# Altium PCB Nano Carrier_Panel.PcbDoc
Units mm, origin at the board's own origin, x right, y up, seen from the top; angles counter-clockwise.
Board outline 171.92 x 183 mm, 4 copper layers (Top, PWR, MID, Bottom), stack 1.612 mm thick; 0 components, 48 nets, 22 pads, 0 vias.
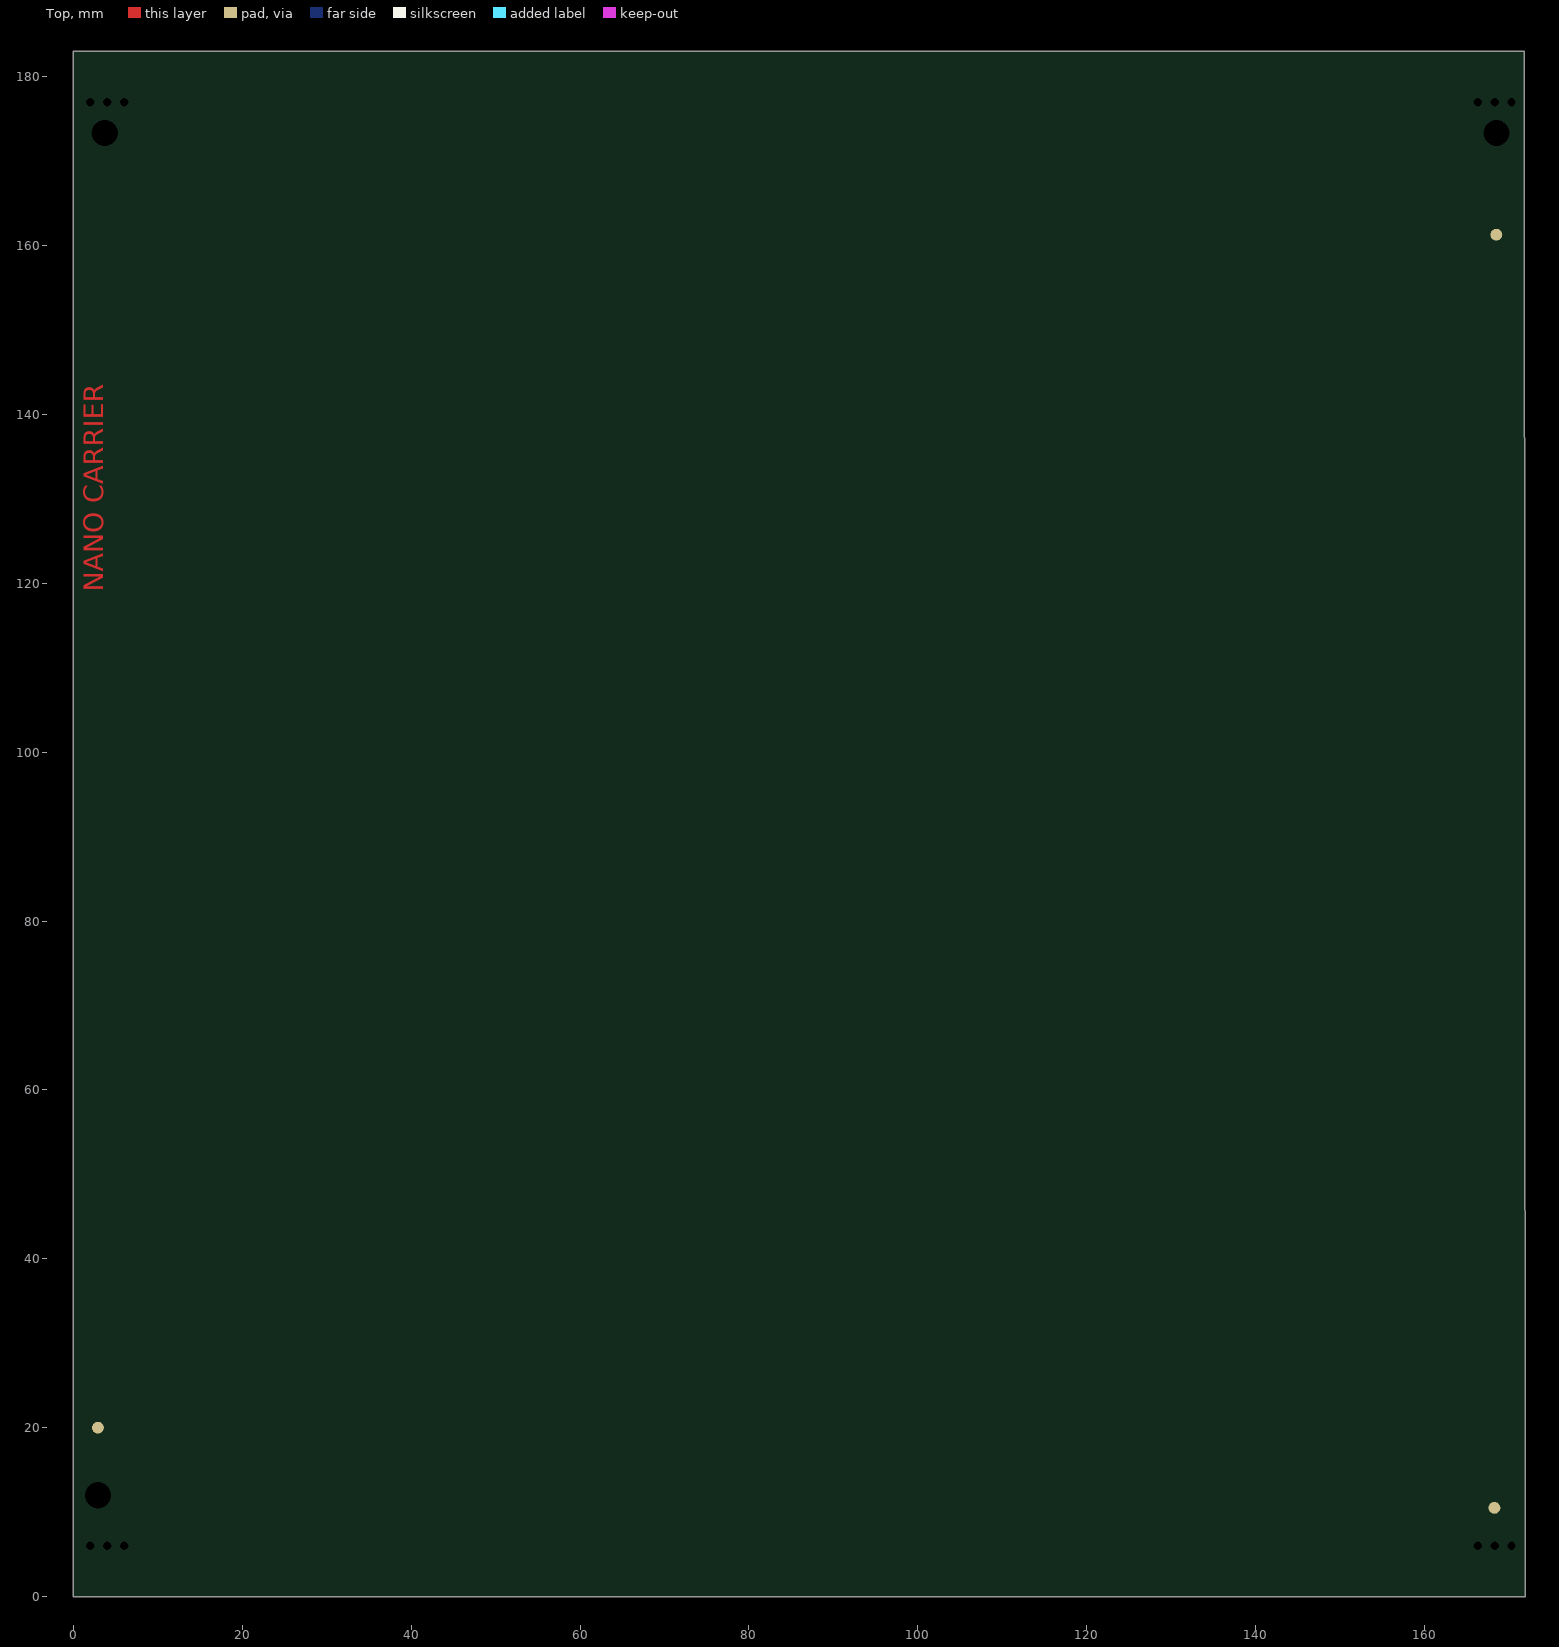
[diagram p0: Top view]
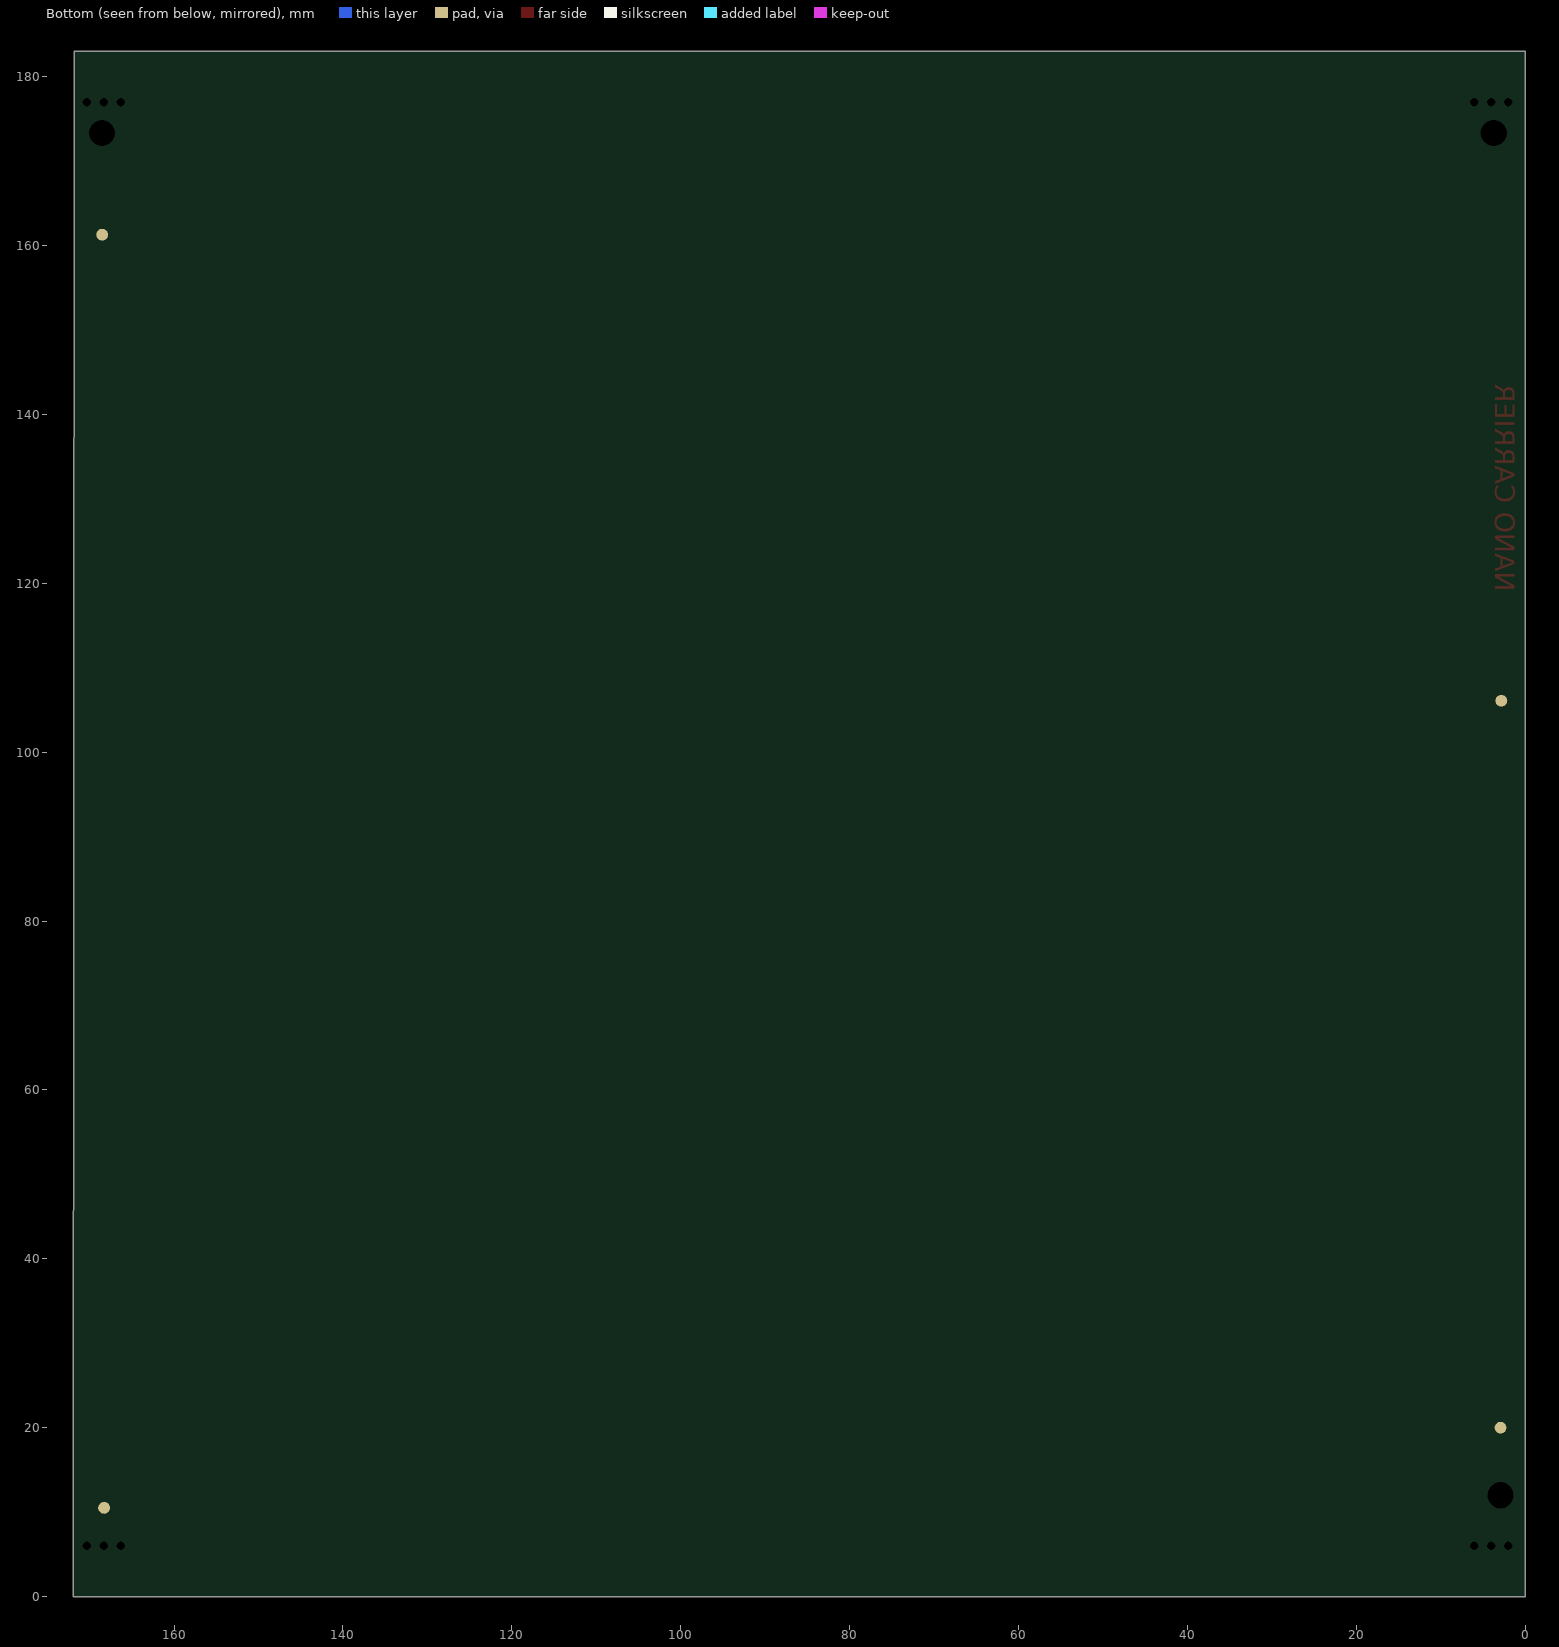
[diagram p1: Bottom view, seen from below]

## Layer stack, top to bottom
Top Solder: solder mask 0.01, Solder Resist, Dk 3.5
Top: signal copper 0.035
Dielectric 1: core 0.356, FR-4, Dk 4.8
PWR: signal copper 0.035
Dielectric3: core 0.76, FR-4, Dk 4.8
MID: signal copper 0.035
Dielectric2: prepreg 0.356, FR-4, Dk 4.8
Bottom: signal copper 0.035
Bottom Solder: solder mask 0.01, Solder Resist, Dk 3.5

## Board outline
171.816,183 0,183 0,0 171.923,0

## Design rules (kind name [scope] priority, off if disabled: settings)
BoardOutlineClearance [not HasFootprint('PH1-15-UA (CASTELL)') and not OnLayer('TopOverlay') and not OnLayer('BottomOverlay')] p1: gap=0.254 ignorepadtopadclearanceinfootprint=FALSE except(0: Arc-SplitContinuation Track-SplitContinuation SMDPad-SplitContinuation THPad-SplitContinuation Via-SplitContinuation Fill-SplitContinuation Poly-SplitContinuation Region-SplitContinuation Text-SplitContinuation)
BoardOutlineClearance mdCopperDimension [not IsKeepOut and not HasFootprint('PH1-15-UA (CASTELL)') and not OnLayer('TopOverlay') and not OnLayer('BottomOverlay')] p2: gap=0.254 ignorepadtopadclearanceinfootprint=FALSE except(0: Arc-SplitContinuation Track-SplitContinuation SMDPad-SplitContinuation THPad-SplitContinuation Via-SplitContinuation Fill-SplitContinuation Poly-SplitContinuation Region-SplitContinuation Text-SplitContinuation)
Clearance Clearance_for_PolygonClass_Isolate_0 [InPolygonClass('Isolate_0')] p1 off: gap=0 ignorepadtopadclearanceinfootprint=FALSE except(0.254: Poly-Hole)
Clearance Clearance_for_PolygonClass_Isolate_3.94 [InPolygonClass('Isolate_3.94')] p2 off: gap=0 ignorepadtopadclearanceinfootprint=FALSE except(0.1: Arc-Poly Track-Poly SMDPad-Poly THPad-Poly Via-Poly Fill-Poly Poly-Poly Poly-Region Poly-Text; 0.254: Poly-Hole)
Clearance [not Keepout vs not Keepout] p3: gap=0.138 ignorepadtopadclearanceinfootprint=TRUE except(0.127: SMDPad-SMDPad SMDPad-THPad SMDPad-Via THPad-THPad THPad-Via Via-Via)
Clearance "Clearance (Same Net)" [All] p4: gap=0 ignorepadtopadclearanceinfootprint=TRUE
Clearance Clearance_for_NetClass_usb [InNetClass('usb') vs InNetClass('usb')] p5: gap=0.127 ignorepadtopadclearanceinfootprint=FALSE
ComponentClearance ComponentClearance_HEADER [InComponent('JP2') or InComponent('JP3') vs InComponent('JP2') or InComponent('JP3')] p1: gap=0 collisioncheckmode=3 verticalgap=0 showdistances=FALSE
ComponentClearance ComponentClearance_1 [All] p2: gap=0.254 collisioncheckmode=3 verticalgap=0.254 showdistances=FALSE
DiffPairsRouting [All] p1: maxlimit=0.3 minlimit=0.1 mostfreqgap=0.254 toplayer_prefgap=0.15 toplayer_minwidth=0.2 toplayer_maxwidth=0.254 toplayer_prefwidth=0.2 midlayer1_maxgap=0.2 midlayer1_prefgap=0.15 midlayer1_minwidth=0.2 midlayer1_maxwidth=0.254 midlayer1_prefwidth=0.2 midlayer2_mingap=0.254 midlayer2_maxgap=0.254 midlayer2_minwidth=0.381 midlayer2_maxwidth=0.381 midlayer2_prefwidth=0.381 bottomlayer_prefgap=0.15 bottomlayer_minwidth=0.2 bottomlayer_maxwidth=0.254 bottomlayer_prefwidth=0.2 maxuncoupledlength=12.7
HoleSize HoleSize_For_NetClass_usb [InNetClass('usb')] p1: absolutevalues=TRUE maxlimit=0.19 minlimit=0.19 maxpercent=80.000 minpercent=20.000
HoleSize [All] p2: absolutevalues=TRUE maxlimit=2540 minlimit=0.19 maxpercent=80.000 minpercent=20.000
HoleToHoleClearance mdDrill [All] p1: gap=0.203 allowstackedmicrovias=TRUE
MinimumSolderMaskSliver [All] p1 off: minsoldermaskwidth=0.254
PasteMaskExpansion Expansion_SMDPaste_OFF [InPadClass('All Pads')] p1: expansion=0
PasteMaskExpansion mlMinCreamFrame [All] p2: expansion=0
PolygonConnect PolygonConnect_For_PolygonThermal_ON_Width100000_Gap100000 [InPolygonClass('PolygonThermal_ON_Width100000_Gap100000') vs Not IsVia] p1: connectstyle=Relief reliefconductorwidth=0.254 reliefentries=4 polygonreliefangle="90 Angle" airgapwidth=0.254
PolygonConnect PolygonConnect_For_PolygonThermal_ON_Width98400_Gap100000 [InPolygonClass('PolygonThermal_ON_Width98400_Gap100000') vs Not IsVia] p2: connectstyle=Relief reliefconductorwidth=0.25 reliefentries=4 polygonreliefangle="90 Angle" airgapwidth=0.254
PolygonConnect ThermalVias [IsVia] p3: connectstyle=Relief reliefconductorwidth=0.254 reliefentries=4 polygonreliefangle="90 Angle" airgapwidth=0.1
PolygonConnect [All] p4: connectstyle=Relief reliefconductorwidth=0.254 reliefentries=4 polygonreliefangle="90 Angle" airgapwidth=0.1
RoomDefinition NANOWANV1_0 [InComponentClass('NANOWANV1_0')] p1 off: confinementstyle=ConfineIn formatcopy=TRUE lockcomponents=FALSE outline -0.592,-0.254 60.495,-0.254 60.495,22.225 -0.592,22.225
RoutingVias [All] p1: holewidth=0.3 width=0.5 viastyle="Through Hole" minholewidth=0.2 minwidth=0.4 maxholewidth=0.5 maxwidth=0.7
SilkToSolderMaskClearance [IsPad] p1 off: minsilkscreentomaskgap=0.254 clearancetoexposedcopper=TRUE
SolderMaskExpansion Expansion_SMDSolder_OFF [InPadClass('SMDSolder_OFF')] p1: expansion=0 istentingtop=FALSE
SolderMaskExpansion mlMinStopFrame [All] p2: expansion=0.102 istentingtop=FALSE
UnRoutedNet [All] p1: checkbadconnections=TRUE
Width Width_For_NetClass_usb [InNetClass('usb')] p1: maxlimit=0.6 minlimit=0.19 preferedwidth=0.254 toplayer_minwidth=0.2 midlayer1_minwidth=0.2 midlayer2_maxwidth=0.254 midlayer2_prefwidth=0.19 bottomlayer_minwidth=0.2 minimp=50.000000 maximp=50.000000 favimp=50.000000
Width [All] p2: maxlimit=254 minlimit=0.1 preferedwidth=0.2 midlayer2_prefwidth=0.152 minimp=50.000000 maximp=50.000000 favimp=50.000000
22 further rules are at their usual default settings.

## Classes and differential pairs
pad class SMDSolder_OFF: U1-EP
pad class SMDPaste_OFF: U1-EP
differential pair USB: +USB_P -USB_N

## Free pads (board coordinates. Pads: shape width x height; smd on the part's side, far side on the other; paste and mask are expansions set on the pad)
  round 1.4 smd far side paste-5 mask+1: 21(2.8,106.1) 21(2.9,20) 21(168.528,161.3)
  round 1.4 smd paste-5 mask+1: 21(2.9,20) 21(168.3,10.5) 21(168.528,161.3)
  round 1.4 smd far side paste+0 mask+1: 21(168.3,10.5)
  round 0 hole 3.1 unplated: 22(2.9,12) 22(3.703,173.351) 22(168.528,173.351)
  round 0 hole 1 unplated: H1(2,6) H1(2,177) H1(4,6) H1(4,177) H1(6,6) H1(6,177) H1(166.325,6) H1(166.325,177) H1(168.325,6) H1(168.325,177) H1(170.325,6) H1(170.325,177)

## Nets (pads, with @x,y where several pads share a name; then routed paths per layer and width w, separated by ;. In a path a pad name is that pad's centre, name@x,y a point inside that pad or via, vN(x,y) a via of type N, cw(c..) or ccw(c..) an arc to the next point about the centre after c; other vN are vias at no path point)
+3V3: 
+3V3_HE: 
+5V: 
+VBUCK: 
A0: 
A1: 
A2: 
A3: 
AREF: 
BOOT0: 
D2: 
D3~: 
D5~: 
D6~: 
D9~: 
D10: 
GND: 
MISO: 
MOSI: 
NetC1_2: 
NetC5_2: 
NetC6_2: 
NetDL1_A: 
NetDL2_A: 
NetL1_1: 
NetM1_4: 
NetM1_10: 
NetM1_20: 
NetM1_45: 
NetM1_46: 
NetM1_47: 
NetM1_48: 
NetQ1_G1: 
NetQ1_S1: 
NetR6_2: 
NetR9_2: 
RESETN: 
RX1: 
SCK: 
SCL: 
SDA: 
SWCLK: 
SWDIO: 
TX1: 
USB_N: 
USB_P: 
VIN: 
VUSB: 

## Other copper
Top:
  text "NANO CARRIER" at 4.3,119 h4 r90

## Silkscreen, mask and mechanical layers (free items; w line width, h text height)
Top Solder:
  text "NANO CARRIER" at 4.3,119 h4 r90
  text "SN" at 170.9,18.6 h4 r90
Drill Guide:
  drawing of 295 lines, arcs and shapes, not listed
  text "Layer" at 193.088,109.344 h1.52
  text "Name" at 203.5,109.344 h1.52
  text "Material" at 227.116,109.344 h1.52
  text "Thickness" at 248.954,109.344 h1.52
  text "Constant" at 265.459,109.344 h1.52
  text "Board Layer Stack" at 279.934,109.344 h1.52
  text "Top Overlay" at 203.5,106.296 h1.52
  text "Top Solder" at 203.5,103.248 h1.52
  text "Solder Resist" at 227.116,103.248 h1.52
  text "0.39mil" at 248.954,103.248 h1.52
  text "3.5" at 265.459,103.248 h1.52
  text "1" at 193.088,100.2 h1.52
  text "Top" at 203.5,100.2 h1.52
  text "Copper" at 227.116,100.2 h1.52
  text "1.38mil" at 248.954,100.2 h1.52
  text "Dielectric 1" at 203.5,97.152 h1.52
  text "FR-4" at 227.116,97.152 h1.52
  text "14.02mil" at 248.954,97.152 h1.52
  text "4.8" at 265.459,97.152 h1.52
  text "2" at 193.088,94.104 h1.52
  text "PWR" at 203.5,94.104 h1.52
  text "Copper" at 227.116,94.104 h1.52
  text "1.38mil" at 248.954,94.104 h1.52
  text "Dielectric3" at 203.5,91.056 h1.52
  text "FR-4" at 227.116,91.056 h1.52
  text "29.92mil" at 248.954,91.056 h1.52
  text "4.8" at 265.459,91.056 h1.52
  text "3" at 193.088,88.008 h1.52
  text "MID" at 203.5,88.008 h1.52
  text "Copper" at 227.116,88.008 h1.52
  text "1.38mil" at 248.954,88.008 h1.52
  text "Dielectric2" at 203.5,84.96 h1.52
  text "FR-4" at 227.116,84.96 h1.52
  text "14.02mil" at 248.954,84.96 h1.52
  text "4.8" at 265.459,84.96 h1.52
  text "4" at 193.088,81.912 h1.52
  text "Bottom" at 203.5,81.912 h1.52
  text "Copper" at 227.116,81.912 h1.52
  text "1.38mil" at 248.954,81.912 h1.52
  text "Bottom Solder" at 203.5,78.864 h1.52
  text "Solder Resist" at 227.116,78.864 h1.52
  text "0.39mil" at 248.954,78.864 h1.52
  text "3.5" at 265.459,78.864 h1.52
  text "Bottom Overlay" at 203.5,75.816 h1.52
Board (Mech12):
  the board outline again, w0.127
Drill Drawing:
  lines w0.254: 192.323,7.13 194.016,7.13 194.016,8.823 192.323,8.823 192.323,7.13
  lines w0.381: 190.804,5.987 343.976,5.987 ; 190.804,13.607 343.976,13.607 ; 204.796,2.177 204.796,17.417 ; 218.255,2.177 218.255,17.417 ; 247.202,2.177 247.202,17.417 ; 260.051,2.177 260.051,17.417 ; 278.69,2.177 278.69,17.417 ; 308.907,2.177 308.907,17.417 ; 323.889,2.177 323.889,17.417 ; 190.804,2.177 343.976,2.177 343.976,17.417 190.804,17.417 190.804,2.177
  text "Symbol" at 193.09,14.75 h1.83
  text "Count" at 205.939,14.75 h1.83
  text "Hole Size" at 219.398,14.75 h1.83
  text "Plated" at 248.345,14.75 h1.83
  text "Hole Type" at 261.194,14.75 h1.83
  text "Drill Layer Pair" at 279.833,14.75 h1.83
  text "Via/Pad" at 310.05,14.75 h1.83
  text "Pad Shape" at 325.032,14.75 h1.83
  text "12" at 205.939,10.94 h1.52
  text "39.37mil (1.000mm)" at 219.398,10.94 h1.52
  text "NPTH" at 248.345,10.94 h1.52
  text "Round" at 261.194,10.94 h1.52
  text "Top - Bottom" at 279.833,10.94 h1.52
  text "Pad" at 310.05,10.94 h1.52
  text "Rounded" at 325.032,10.94 h1.52
  text "A" at 192.351,10.686 h1.69
  text "3" at 205.939,7.13 h1.52
  text "122.05mil (3.100mm)" at 219.398,7.13 h1.52
  text "NPTH" at 248.345,7.13 h1.52
  text "Round" at 261.194,7.13 h1.52
  text "Top - Bottom" at 279.833,7.13 h1.52
  text "Pad" at 310.05,7.13 h1.52
  text "Rounded" at 325.032,7.13 h1.52
  text "15 Total" at 205.939,3.32 h1.52

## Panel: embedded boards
"Nano_Carrier.PcbDoc" at 8.9,7, 2 rows x 3 columns, spacing 89 x 52, rotation 0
